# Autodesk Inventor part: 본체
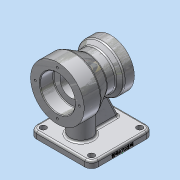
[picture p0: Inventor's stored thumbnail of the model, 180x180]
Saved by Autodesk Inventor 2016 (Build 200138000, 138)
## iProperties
Created: 2019-01
Part Number: 본체
Material: 알루미늄 6061
Document SubType Name: Modeling
Designer: MIRAE
Density: 2.7 g/cm^3
Appearance: 알루미늄 - 평지
Mass: 898.821 g
Surface Area: 600.961 cm^2
Volume: 332.897 cm^3
Author: MIRAE
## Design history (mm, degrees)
sketch "스케치1"
  geometry: L1 (-46, 46)-(46, 46); L2 (46, 46)-(46, -46); L3 (46, -46)-(-46, -46); L4 (-46, -46)-(-46, 46); L5 (-46, 46)-(46, -46); L6 (46, 46)-(-46, -46); 1 further point
  constraints: 12 end point, 2 midpoint, 2 parallel, 1 horizontal, 1 perpendicular
  dimensions: "d0" = 92 distance of L2.end L3.end; "d1" = 92 distance of L1.end L2.end
extrude "돌출1" new body sketch "스케치1" distance "d2" = 10; taper "d3" = 0 deg
sketch "스케치2"
  geometry: L1 (-51, 80)-(29, 80); L2 (-46, 0)-(-46, 10) reference; L3 (-46, 0)-(46, 0) reference; L4 (-51, 80)-(-51, 120); L5 (-51, 120)-(-26, 120); L6 (-26, 120)-(-5.215, 108); L7 (-5.215, 108)-(8.126, 108); L8 (8.126, 108)-(14, 115); L9 (14, 115)-(29, 115); L10 (29, 115)-(29, 80); 1 further point
  constraints: 16 end point, 2 parallel, 2 perpendicular, 1 horizontal, 1 vertical
  dimensions: "d4" = 5 distance from line of L2 L1.start; "d5" = 80 distance of L1.start L1.end; "d6" = 80 distance between parallel lines of L3 L1; "d7" = 80 diameter of L5 L1; "d8" = 70 diameter of L9 L1; "d9" = 56 diameter of L7 L1; "d10" = 25 distance of L4.end L5.end; "d11" = 15 distance of L8.end L9.end; "d12" = 30 deg angle of L7 L6; "d13" = 50 deg angle of L7 L8
revolve "회전1" sketch "스케치2" stored, may be unused: angle "d14" = 90 deg
sketch "스케치3"
  geometry: L1 (-51, 40)-(-51, 120) reference; L2 (-51, 80)-(29, 80); L3 (29, 45)-(29, 115) reference; L4 (-51, 80)-(-51, 106); L5 (-51, 106)-(-31, 106); L6 (-31, 106)-(-31, 96); L7 (-31, 96)-(12, 96); L8 (12, 96)-(12, 100); L9 (12, 100)-(29, 100); L10 (29, 80)-(29, 100); 1 further point
  constraints: 16 end point, 5 perpendicular, 2 midpoint, 2 point on line, 1 horizontal
  dimensions: "d15" = 20 distance of L4.end L5.end; "d16" = 17 distance of L8.end L9.end; "d17" = 52 diameter of L5 L2; "d18" = 32 diameter of L7 L2; "d19" = 40 diameter of L9 L2
revolve "회전2" sketch "스케치3" stored, may be unused: angle "d20" = 90 deg
sketch "스케치4"
  geometry: L1 (46, -46)-(-46, -46) reference; L2 (-46, -46)-(-46, 46) reference; C1 r 16 at (0, -16); 1 further point
  constraints: 1 centre point
  dimensions: "d21" = 32 diameter of C1; "d23" = 30 distance from line of C1.centre L1; "d24" = 46 distance from line of L2 C1.centre
extrude "돌출2" join sketch "스케치4" stored distance "d25" = 10; taper "d26" = 0 deg
sketch "스케치5"
  geometry: L1 (14, 45)-(29, 45) reference; L2 (19.679, 45)-(36, 10); L3 (-46, 10)-(46, 10) reference; L4 (46, 0)-(46, 10) reference; L5 (8.126, 52)-(14, 45) reference; L6 (0, 52)-(8.126, 52) reference; L7 (0, 10)-(0, 52) reference; 1 further point
  constraints: 2 end point, 2 point on line
  dimensions: "d27" = 10 distance from line of L4 L2.end; "d28" = 25 deg angle of L4 L2
feature "리브1" sketch "스케치5" dims "d29" = 1, "d30" = 10, "d31" = 0, "d32" = 0, "d33" = 1, "d34" = 1
sketch "스케치6"
  geometry: 1 further point
fillet "모깎기1" dims "d35" = 10
sketch "스케치7"
  geometry: A1 r 10 centre (36, -36) between (36, -46) and (46, -36) reference; A2 r 10 centre (-36, -36) between (-46, -36) and (-36, -46) reference; A3 r 10 centre (-36, 36) between (-36, 46) and (-46, 36) reference; A4 r 10 centre (36, 36) between (46, 36) and (36, 46) reference; 5 further points
  constraints: 4 coincident
hole "구멍1" sketch "스케치7" at (36, 36), (-36, 36), (-36, -36), (36, -36) diameter "d36" = 9; stored, may be unused: countersink angle "d40" = 90 deg, drill point angle "d42" = 0 deg; dims "d37" = 6, "d38" = 4, "d39" = 2, "d41" = 8
sketch "스케치8" dims "d43" = 66
  geometry: 3 further points
  constraints: 1 vertical alignment, 2 other
hole "구멍2" sketch "스케치8" at (0, 33) diameter "d44" = 3.242; stored, may be unused: countersink angle "d48" = 90 deg, drill point angle "d50" = 118 deg; dims "d45" = 9, "d46" = 4, "d47" = 2, "d49" = 11
sketch "스케치9" dims "d54" = 55
  geometry: 3 further points
  constraints: 1 vertical alignment, 2 other
hole "구멍3" sketch "스케치9" at (0, -27.5) diameter "d55" = 3.242; stored, may be unused: countersink angle "d59" = 90 deg, drill point angle "d61" = 118 deg; dims "d56" = 9, "d57" = 4, "d58" = 2, "d60" = 11
sketch "스케치10"
  geometry: 1 further point
fillet "모깎기2" dims "d65" = 3
sketch "스케치11"
  geometry: L1 (0, 82)-(0, 72) reference; L2 (-7, -10)-(0, -10) reference; 2 further points
  constraints: 1 other
  dimensions: "d66" = 4 distance from line of L1 point (-4, 36); "d67" = 46 distance from line of L2 point (-4, 36)
feature "엠보싱1" sketch "스케치11" dims "d0" = 92, "d1" = 92, "d68" = 0.5, "d69" = 0
chamfer "모따기1" distance "d70" = 1; stored, may be unused: second distance "d71" = 2, angle "d72" = 45 deg
chamfer "모따기2" distance "d73" = 1; stored, may be unused: second distance "d74" = 2, angle "d75" = 45 deg
fillet "모깎기3" dims "d76" = 0.6
fillet "모깎기4" dims "d77" = 1
fillet "모깎기6" dims "d79" = 3
fillet "모깎기7" dims "d80" = 3
fillet "모깎기8" dims "d81" = 3
fillet "모깎기9" dims "d82" = 3
feature "분할1"
node "솔리드1"
pattern_circular "원형 패턴1" dims angle "d52" = 360 deg
pattern_circular "원형 패턴2" dims angle "d63" = 360 deg
